Omron CX-Programmer project NewProject (CX-Programmer 7.11)

# PLC NewPLC1: CJ1M CPU11
I/O table (CPU CJ1M-CPU11): rack 0 slot 0 CJ1W-ETN21(ETN21Mode); rack 0 slot 1 CJ1W-ID211; rack 0 slot 2 CJ1W-OC211; rack 0 slot 3 CJ1W-ETN21(ETN21Mode)

## Program NewProgram1 (cyclic task 0)

### Section Section1

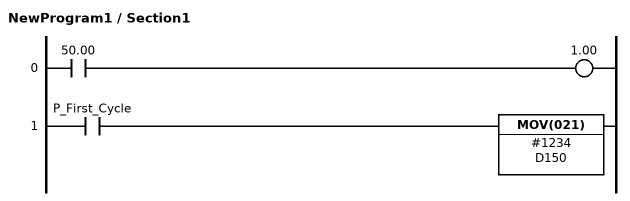
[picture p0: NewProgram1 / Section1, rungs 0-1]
; rung 0
LD 50.00
OUT 1.00
; rung 1
LD P_First_Cycle
MOV(021) #1234 D150

### Section END
; rung 0
END(001)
